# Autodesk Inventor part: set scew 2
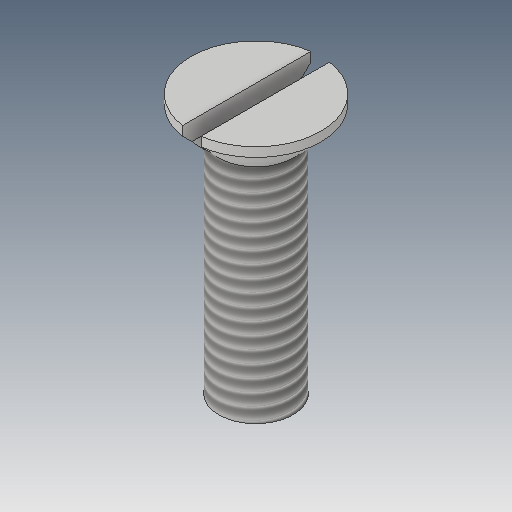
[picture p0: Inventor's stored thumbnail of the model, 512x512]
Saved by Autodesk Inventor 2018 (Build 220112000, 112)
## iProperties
Created: 2016-06
Part Number: set scew 2
Material: Generic
Document SubType Name: Modeling
Designer: CADCIM
Density: 1 g/cm^3
Appearance: Default
Author: CADCIM
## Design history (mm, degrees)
sketch "Sketch1"
  geometry: C1 r 3 at (0, 0); 1 further point
  constraints: 1 centre point, 1 coincident
  dimensions: "d0" = 6 diameter of C1
extrude "Extrusion1" new body sketch "Sketch1" distance "d1" = 18; taper "d2" = 0 deg
sketch "Sketch2"
  geometry: L1 (18, -3)-(18, 3) reference; L2 (18, 0)-(18, -3); L3 (18, -3)-(21, -6); L4 (21, -6)-(21, 0); L5 (21, 0)-(18, 0); 1 further point
  constraints: 8 end point, 2 vertical, 1 midpoint, 1 perpendicular
  dimensions: "d4" = 3 distance of L2.start L2.end; "d5" = 6 distance of L4.end L3.end; "d6" = 3 distance from line of L1.start L4
revolve "Revolution1" sketch "Sketch2" stored, may be unused: angle "d7" = 90 deg
sketch "Sketch3"
  geometry: C1 r 5.25 at (0, 0); 1 further point
  constraints: 1 centre point, 1 coincident
  dimensions: "d8" = 10.5 diameter of C1
extrude "Extrusion2" sketch "Sketch3" distance "d9" = 26.75; taper "d10" = 0 deg
sketch "Sketch4"
  geometry: L1 (-0.75, 8.347)-(0.75, 8.347); L2 (0.75, 8.347)-(0.75, -8.125); L3 (0.75, -8.125)-(-0.75, -8.125); L4 (-0.75, -8.125)-(-0.75, 8.347); L5 (0, 0)-(0, 6.165)
  constraints: 10 end point, 3 parallel, 1 horizontal, 1 perpendicular, 1 other
  dimensions: "d11" = 1.5 distance of L1.start L1.end
extrude "Extrusion3" cut sketch "Sketch4" distance "d12" = 1.5; taper "d13" = 0 deg
sketch "Sketch5"
  geometry: L1 (0, 0)-(0, 3); L2 (0, 3)-(-1.732, 0); L3 (-1.732, 0)-(0, 0); L4 (0, 3)-(0, -3) reference; 1 further point
  constraints: 6 end point, 2 midpoint, 1 perpendicular, 1 point on line, 1 vertical
  dimensions: "d21" = 60 deg angle of L2 L3; "d22" = 3 distance of L1.start L1.end
thread "Thread2" dims "d19" = 10, "d20" = 0
revolve "Revolution3" stored, may be unused: angle "d23" = 90 deg
body "Solid1"
